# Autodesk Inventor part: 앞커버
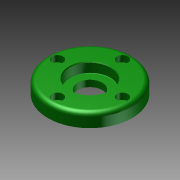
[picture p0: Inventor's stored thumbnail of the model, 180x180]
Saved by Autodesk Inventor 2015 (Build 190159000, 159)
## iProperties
Created: 2025-08
Part Number: 앞커버
Material: 일반
Document SubType Name: Modeling
Designer: USER
Density: 1 g/cm^3
Appearance: 기본값
Author: USER
Author: jhkim
Creation Date: 2025-08-05
Sending System: Autodesk Inventor 2026
Preprocessor: ST-DEVELOPER v20.1
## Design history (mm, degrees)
node "앞커버1"
node "솔리드1"
node "기준1"
